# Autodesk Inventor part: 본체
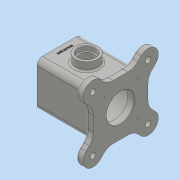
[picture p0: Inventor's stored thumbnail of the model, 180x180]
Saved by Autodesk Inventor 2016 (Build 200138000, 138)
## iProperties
Created: 2019-11
Part Number: 본체
Material: 일반
Document SubType Name: Modeling
Designer: user
Density: 1 g/cm^3
Appearance: 기본값
Mass: 398.608 g
Surface Area: 879.568 cm^2
Volume: 398.608 cm^3
Author: user
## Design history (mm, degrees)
sketch "스케치1"
  geometry: L1 (-40, 40)-(40, 40); L2 (40, 40)-(40, -40); L3 (40, -40)-(-40, -40); L4 (-40, -40)-(-40, 40); L5 (-40, 40)-(40, -40); L6 (40, 40)-(-40, -40); 1 further point
  constraints: 12 end point, 2 midpoint, 2 parallel, 1 horizontal, 1 perpendicular
  dimensions: "d1" = 80 distance of L1.end L2.end; "d77" = 80 distance of L2.end L3.end
extrude "돌출1" new body sketch "스케치1" distance "d2" = 98; taper "d3" = 0 deg
sketch "스케치2"
  geometry: L1 (-49, 49)-(49, 49); L2 (49, 49)-(49, -49); L3 (49, -49)-(-49, -49); L4 (-49, -49)-(-49, 49); L5 (-49, 49)-(49, -49); L6 (49, 49)-(-49, -49); L7 (-49.497, 49.497)-(49.497, -49.497); L8 (-62.225, 36.77)-(36.77, -62.225); L9 (62.225, -36.77)-(-36.77, 62.225); L10 (49.497, 49.497)-(-49.497, -49.497); L11 (36.77, 62.225)-(-62.225, -36.77); L12 (-36.77, -62.225)-(62.225, 36.77); A1 r 18 centre (-49.497, 49.497) between (-36.77, 62.225) and (-62.225, 36.77); A2 r 18 centre (49.497, -49.497) between (36.77, -62.225) and (62.225, -36.77); A3 r 18 centre (49.497, 49.497) between (62.225, 36.77) and (36.77, 62.225); A4 r 18 centre (-49.497, -49.497) between (-62.225, -36.77) and (-36.77, -62.225); 5 further points
  constraints: 28 end point, 8 point on circle, 8 tangent, 6 midpoint, 4 centre point, 4 parallel, 2 coincident, 2 perpendicular, 1 collinear, 1 horizontal
  dimensions: "d4" = 98 distance of L1.start L1.end; "d5" = 98 distance of L1.end L2.end; "d6" = 140 distance of L7.start L7.end; "d7" = 18 radius of A1; "d8" = 140 distance of L10.start L10.end; "d9" = 18 radius of A3
extrude "돌출2" join sketch "스케치2" distance "d10" = 12; taper "d11" = 0 deg
node "작업 평면1"
sketch "스케치3"
  geometry: C1 r 20 at (0, 49); 1 further point
  constraints: 1 centre point
  dimensions: "d13" = 49 distance of point (0, 0) C1.centre; "d14" = 40 diameter of C1
extrude "돌출3" join sketch "스케치3" stored distance "d15" = 12; taper "d16" = 0 deg
sketch "스케치4"
  geometry: L1 (40, 98)-(-40, 98) reference; L2 (0, 98)-(25, 98); L3 (25, 98)-(25, 86); L4 (25, 86)-(0, 86); L5 (0, 86)-(0, 98); L6 (0, 86)-(35, 86); L7 (35, 86)-(35, 0); L8 (35, 0)-(0, 0); L9 (0, 0)-(0, 86); L10 (-23.544, -12)-(23.544, -12) reference; L11 (0, 0)-(25, 0); L12 (25, 0)-(25, -12); L13 (25, -12)-(0, -12); L14 (0, -12)-(0, 0); 1 further point
  constraints: 24 end point, 6 parallel, 3 horizontal, 3 perpendicular, 1 midpoint, 1 point on line
  dimensions: "d17" = 50 diameter of L3 L5; "d18" = 70 diameter of L7 L9; "d19" = 50 diameter of L12 L14; "d20" = 12 distance of L2.end L3.end; "d21" = 86 distance of L6.end L7.end
revolve "회전1" sketch "스케치4" stored, may be unused: angle "d22" = 90 deg
sketch "스케치5"
  geometry: C1 r 20 at (0, 0) reference; 1 further point
hole "구멍1" sketch "스케치5" at (0, 0) diameter "d23" = 30; stored, may be unused: countersink angle "d27" = 90 deg, drill point angle "d29" = 0 deg; dims "d24" = 6, "d25" = 4, "d26" = 2, "d28" = 8
sketch "스케치6"
  geometry: C1 r 15 at (0, 0) reference; 1 further point
hole "구멍2" sketch "스케치6" at (0, 0) diameter "d30" = 25; stored, may be unused: countersink angle "d34" = 90 deg, drill point angle "d36" = 0 deg; dims "d31" = 6, "d32" = 4, "d33" = 2, "d35" = 30
sketch "스케치7"
  geometry: L1 (-30, 30)-(30, 30); L2 (30, 30)-(30, -30); L3 (30, -30)-(-30, -30); L4 (-30, -30)-(-30, 30); L5 (-30, 30)-(30, -30); L6 (30, 30)-(-30, -30); C1 r 35 at (0, 0) reference; 2 further points
  constraints: 12 end point, 2 midpoint, 2 parallel, 1 coincident, 1 horizontal, 1 perpendicular
  dimensions: "d37" = 60 distance of L1.start L1.end; "d38" = 60 distance of L1.end L2.end
hole "구멍3" sketch "스케치7" at (-30, 30) diameter "d39" = 3.242; stored, may be unused: countersink angle "d43" = 90 deg, drill point angle "d45" = 118 deg; dims "d40" = 8, "d41" = 4, "d42" = 2, "d44" = 10
sketch "스케치8"
  geometry: 1 further point
hole "구멍4" sketch "스케치8" at (-30, 30) diameter "d49" = 3.242; stored, may be unused: countersink angle "d53" = 90 deg, drill point angle "d55" = 118 deg; dims "d50" = 8, "d51" = 4, "d52" = 2, "d54" = 10
sketch "스케치9"
  geometry: L1 (-36.77, 62.225)-(-23.544, 49) reference; L2 (-49, 23.544)-(-62.225, 36.77) reference; L3 (-49, 23.544)-(-49, -23.544) reference; L4 (-62.225, -36.77)-(-49, -23.544) reference; L5 (-23.544, -49)-(-36.77, -62.225) reference; L6 (-23.544, -49)-(23.544, -49) reference; L7 (36.77, -62.225)-(23.544, -49) reference; L8 (49, -23.544)-(62.225, -36.77) reference; L9 (49, -23.544)-(49, 23.544) reference; L10 (62.225, 36.77)-(49, 23.544) reference; L11 (23.544, 49)-(36.77, 62.225) reference; L12 (23.544, 49)-(-23.544, 49) reference; L13 (40, 40)-(40, -40) reference; L14 (40, -40)-(-40, -40) reference; L15 (-40, -40)-(-40, 40) reference; L16 (-40, 40)-(40, 40) reference; A1 r 18 centre (-49.497, 49.497) between (-36.77, 62.225) and (-62.225, 36.77) reference; A2 r 18 centre (-49.497, -49.497) between (-62.225, -36.77) and (-36.77, -62.225) reference; A3 r 18 centre (49.497, -49.497) between (36.77, -62.225) and (62.225, -36.77) reference; A4 r 18 centre (49.497, 49.497) between (62.225, 36.77) and (36.77, 62.225) reference; 1 further point
hole "구멍5" sketch "스케치9" at (-49.497, 49.497), (49.497, 49.497), (-49.497, -49.497), (49.497, -49.497) diameter "d59" = 10; stored, may be unused: countersink angle "d63" = 90 deg, drill point angle "d65" = 0 deg; dims "d60" = 8, "d61" = 18, "d62" = 4, "d64" = 10
fillet "모깎기1" dims "d66" = 10
fillet "모깎기2" dims "d67" = 25
fillet "모깎기3" dims "d68" = 3
chamfer "모따기1" distance "d69" = 1; stored, may be unused: second distance "d70" = 2, angle "d71" = 45 deg
sketch "스케치10" dims "d1" = 80, "d77" = 80
  geometry: L1 (60, 0)-(0, 0) reference; C1 r 12.5 at (30, 49) reference; 2 further points
  constraints: 1 vertical alignment, 1 other
  dimensions: "d72" = 10 distance from line of point (30, 10) L1
feature "엠보싱1" sketch "스케치10" dims "d1" = 80, "d73" = 0.5, "d74" = 0, "d77" = 80
node "솔리드1"
pattern_circular "원형 패턴1" dims angle "d47" = 360 deg
pattern_circular "원형 패턴2" dims angle "d57" = 360 deg
node "투영된 루프1"
node "투영된 루프2"
node "투영된 루프3"
other parameters: "d12" = 55
